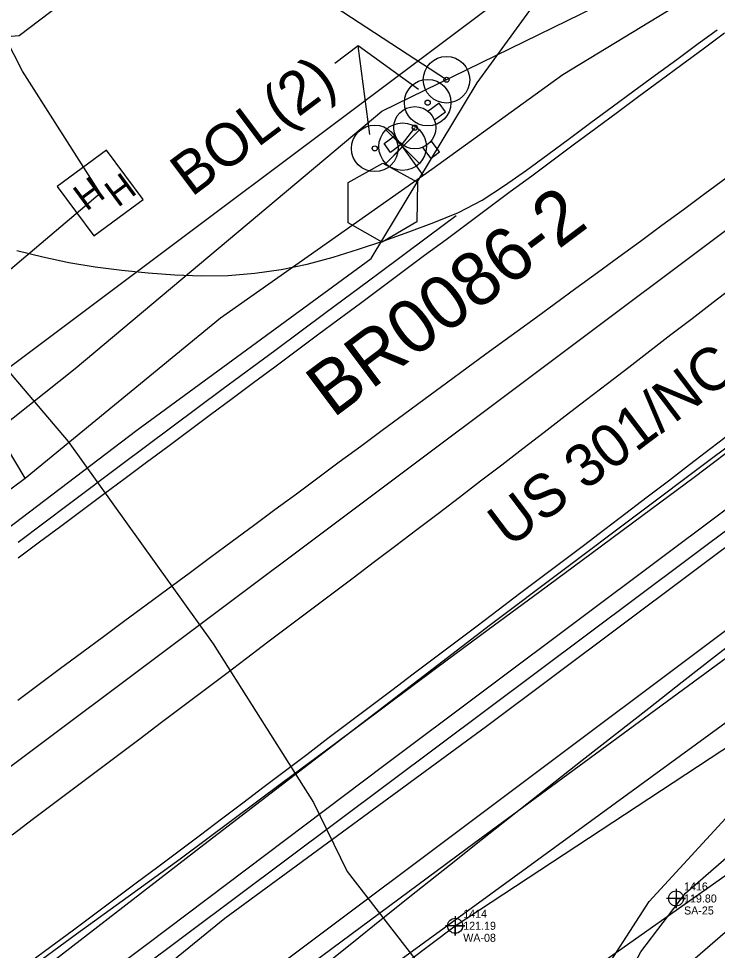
# Model space of a CAD drawing. Extents: x 2186615 to 2188822, y 629899 to 631820.
# Drawn here: x 2187187.8 to 2187253.2, y 630398.8 to 630486.1 of the extents above; entities that cross this region are included whole.
import ezdxf

# ---------------------------------------------------------------- set-up
doc = ezdxf.new("R2010")
doc.units = 0
for name, color, linetype in [('CTL Primary Horizontal and Vertical CELL', 7, 'Continuous'), ('CTL Primary Horizontal and Vertical Text', 7, 'Continuous'), ('Exist Environmental Wetland Boundary', 7, 'Continuous'), ('Exist Environmental Wetland Boundary Cogo Comment', 7, 'Continuous'), ('Exist Environmental Wetland Boundary Cogo Elevation', 7, 'Continuous'), ('Exist Environmental Wetland Boundary Cogo Number', 7, 'Continuous'), ('Exist Environmental Wetland Boundary Cogo Point CELL', 7, 'Continuous'), ('Exist Guardrail', 7, 'Continuous'), ('Exist Horizontal Alignment', 7, 'Continuous'), ('Exist Hydro Jurisdictional Stream or Body of Water', 7, 'Continuous'), ('Exist Other Culture Area Outline Leader', 7, 'Continuous'), ('Exist Other Culture Located Object CELL', 7, 'Continuous'), ('Exist Other Culture Located Object Leader', 7, 'Continuous'), ('Exist Other Culture Located Object Text', 7, 'Continuous'), ('Exist Right of Way Line', 7, 'Continuous'), ('Exist Roads EOP', 7, 'Continuous'), ('Exist Roads EOP Text', 7, 'Continuous'), ('Exist Roads EOT', 7, 'Continuous'), ('Exist Utilities Gas UG Line SUE LOS B', 7, 'Continuous'), ('Exist Utilities Sanitary Sewer UG Line', 7, 'Continuous'), ('Exist Utilities Telephone UG Cable SUE LOS C', 7, 'Continuous'), ('Exist Utilities Telephone UG FO SUE LOS B', 7, 'Continuous'), ('Exist Utilities TV Hand Hole CELL', 7, 'Continuous'), ('Exist Utilities TV UG FO Cable SUE LOS B', 7, 'Continuous'), ('Exist Utilities Water Fire Hydrant CELL', 7, 'Continuous'), ('Exist Utilities Water UG Line SUE LOS B', 7, 'Continuous'), ('Exist Utilities Water Valve CELL', 7, 'Continuous'), ('Exist Vegetation Woods Line', 7, 'Continuous'), ('Scratch_Level_1', 7, 'Continuous')]:
    doc.layers.add(name, color=color, linetype=linetype)

msp = doc.modelspace()

# ---------------------------------------------------------------- linework, layer by layer
at = {"layer": 'CTL Primary Horizontal and Vertical CELL'}
msp.add_line((2187221.866, 630468.879), (2187221.866, 630468.879), dxfattribs=at)
msp.add_lwpolyline([(2187218.634, 630470.75), (2187221.884, 630472.563), (2187225.134, 630470.775), (2187225.084, 630467.05), (2187221.834, 630465.163), (2187218.634, 630466.975)], close=True, dxfattribs=at)
at = {"layer": 'Exist Environmental Wetland Boundary'}
for points in [[(2187200.333, 630357.676), (2187218.012, 630369.88), (2187243.865, 630391.755), (2187268.738, 630413.3), (2187284.769, 630424.116), (2187304.062, 630440.889), (2187311.728, 630449.237), (2187310.985, 630450.407)], [(2187091.311, 630271.672), (2187085.676, 630287.812), (2187098.271, 630306.167), (2187117.246, 630318.391), (2187145.167, 630331.818), (2187167.383, 630352.861), (2187202.427, 630381.298), (2187228.671, 630401.09), (2187258.21, 630420.516), (2187282.166, 630435.853)]]:
    msp.add_lwpolyline(points, dxfattribs=at)
at = {"layer": 'Exist Environmental Wetland Boundary Cogo Point CELL'}
for points in [[(2187249.362, 630404.547), (2187249.362, 630402.747), (2187249.362, 630403.647), (2187250.262, 630403.647), (2187248.462, 630403.647)], [(2187228.671, 630401.99), (2187228.671, 630400.19), (2187228.671, 630401.09), (2187229.571, 630401.09), (2187227.771, 630401.09)]]:
    msp.add_lwpolyline(points, dxfattribs=at)
for centre in [(2187249.362, 630403.647), (2187228.671, 630401.09)]:
    msp.add_circle(centre, 0.703, dxfattribs=at)
at = {"layer": 'Exist Guardrail'}
msp.add_lwpolyline([(2187434.115, 630575.844), (2187413.642, 630560.327), (2187392.389, 630544.34), (2187371.189, 630528.329), (2187353.022, 630514.54), (2187332.378, 630498.862), (2187308.035, 630480.517), (2187282.875, 630461.57), (2187260.432, 630444.878), (2187240.787, 630430.164), (2187221.99, 630416.084), (2187199.867, 630399.404), (2187178.435, 630383.307), (2187159.654, 630369.054), (2187143.316, 630356.53), (2187128.809, 630345.412), (2187116.826, 630336.517)], dxfattribs=at)
at = {"layer": 'Exist Horizontal Alignment'}
msp.add_line((2187136.406, 630378.107), (2188520.855, 631416.042), dxfattribs=at)
at = {"layer": 'Exist Hydro Jurisdictional Stream or Body of Water'}
for points in [[(2187197.322, 630361.43), (2187213.945, 630373.562), (2187222.659, 630386.877), (2187241.705, 630395.38), (2187246.836, 630403.358), (2187255.086, 630412.327), (2187267.186, 630417.823), (2187275.409, 630422.294), (2187281.209, 630428.913), (2187281.92, 630435.898), (2187289.055, 630441.644), (2187305.984, 630451.32), (2187327.255, 630464.456), (2187344.34, 630479.914), (2187359.178, 630488.147), (2187368.792, 630495.674), (2187384.724, 630510.856), (2187399.768, 630521.857), (2187428.248, 630541.272), (2187449.565, 630557.041)], [(2187200.333, 630357.676), (2187217.66, 630373.541), (2187219.417, 630375.085), (2187222.068, 630380.972), (2187226.921, 630384.519), (2187239.946, 630392.223), (2187243.455, 630393.717), (2187246.058, 630398.658), (2187250.235, 630404.156), (2187257.633, 630410.563), (2187272.327, 630417.422), (2187280.629, 630425.711), (2187291.154, 630437.828), (2187309.311, 630449.202), (2187326.618, 630461.663), (2187344.871, 630475.57), (2187361.058, 630486.179), (2187383.779, 630505.824), (2187403.688, 630519.913), (2187435.685, 630540.516), (2187447.835, 630554.369)]]:
    msp.add_lwpolyline(points, dxfattribs=at)
at = {"layer": 'Exist Other Culture Area Outline Leader'}
msp.add_lwpolyline([(2187168.926, 630482.94), (2187187.799, 630484.536), (2187191.69, 630487.453)], dxfattribs=at)
at = {"layer": 'Exist Other Culture Located Object CELL'}
for centre, radius in [((2187227.853, 630480.376), 2.18), ((2187226.09, 630478.227), 2.18), ((2187227.853, 630480.376), 0.24), ((2187226.09, 630478.227), 0.24), ((2187221.132, 630473.943), 2.18), ((2187221.132, 630473.943), 0.24)]:
    msp.add_circle(centre, radius, dxfattribs=at)
at = {"layer": 'Exist Other Culture Located Object Leader'}
for points in [[(2187227.853, 630480.376), (2187217.435, 630487.187), (2187220.582, 630489.546)], [(2187220.664, 630475.256), (2187219.59, 630483.548), (2187217.402, 630481.907)], [(2187225.219, 630479.456), (2187219.59, 630483.548), (2187217.402, 630481.907)]]:
    msp.add_lwpolyline(points, dxfattribs=at)
at = {"layer": 'Exist Right of Way Line'}
for p, q in [((2187118.411, 630402.11), (2188502.827, 631440.021)), ((2187154.402, 630354.104), (2188538.851, 631392.039))]:
    msp.add_line(p, q, dxfattribs=at)
msp.add_arc((2189028.8, 628141.736), 2893.554, 125.65722, 135.708207, dxfattribs=at)
at = {"layer": 'Exist Roads EOP'}
for points in [[(2187187.603, 630464.38), (2187190.032, 630463.786), (2187192.475, 630463.257), (2187194.94, 630462.842), (2187197.422, 630462.539), (2187199.908, 630462.289), (2187202.4, 630462.098), (2187204.898, 630461.996), (2187207.397, 630462.034), (2187209.889, 630462.236), (2187212.363, 630462.597), (2187214.812, 630463.099), (2187217.228, 630463.739), (2187219.614, 630464.485), (2187221.979, 630465.293), (2187224.331, 630466.139), (2187226.673, 630467.014), (2187228.994, 630467.934), (2187231.212, 630469.087), (2187233.299, 630470.463), (2187235.339, 630471.908), (2187237.359, 630473.381), (2187239.369, 630474.867), (2187241.374, 630476.36), (2187243.38, 630477.852), (2187245.395, 630479.331), (2187247.411, 630480.81), (2187249.427, 630482.288), (2187251.443, 630483.766), (2187253.221, 630485.07)], [(2187187.729, 630437.045), (2187192.512, 630440.668), (2187197.316, 630444.262), (2187202.127, 630447.846), (2187206.939, 630451.431), (2187211.753, 630455.012), (2187216.569, 630458.591), (2187221.385, 630462.169), (2187226.201, 630465.747), (2187228.775, 630467.658)], [(2187255.836, 630446.736), (2187251.071, 630443.09), (2187246.246, 630439.524), (2187241.419, 630435.961), (2187236.591, 630432.398), (2187231.763, 630428.836), (2187226.945, 630425.261), (2187222.134, 630421.675), (2187217.324, 630418.089), (2187212.513, 630414.504), (2187207.703, 630410.918), (2187202.884, 630407.343), (2187198.03, 630403.816), (2187193.174, 630400.292), (2187188.329, 630396.753), (2187183.51, 630393.178)]]:
    msp.add_lwpolyline(points, dxfattribs=at)
at = {"layer": 'Exist Roads EOT'}
for points in [[(2187187.706, 630435.563), (2187189.71, 630437.058), (2187191.714, 630438.553), (2187193.718, 630440.047), (2187195.723, 630441.54), (2187197.729, 630443.033), (2187199.734, 630444.525), (2187201.739, 630446.018), (2187203.745, 630447.511), (2187205.75, 630449.003), (2187207.756, 630450.496), (2187209.761, 630451.989), (2187211.767, 630453.481), (2187213.772, 630454.974), (2187215.778, 630456.466), (2187217.783, 630457.959), (2187219.789, 630459.452), (2187221.795, 630460.943), (2187223.801, 630462.435), (2187225.808, 630463.926), (2187227.815, 630465.417), (2187229.822, 630466.907), (2187231.828, 630468.398), (2187233.835, 630469.889), (2187235.842, 630471.38), (2187237.848, 630472.871), (2187239.855, 630474.362), (2187241.862, 630475.852), (2187243.87, 630477.342), (2187245.879, 630478.829), (2187247.889, 630480.316), (2187249.898, 630481.802), (2187251.908, 630483.289), (2187253.918, 630484.775)], [(2187187.68, 630422.229), (2187189.685, 630423.723), (2187191.69, 630425.217), (2187193.695, 630426.71), (2187195.701, 630428.201), (2187197.71, 630429.69), (2187199.719, 630431.177), (2187201.729, 630432.663), (2187203.739, 630434.149), (2187205.749, 630435.636), (2187207.759, 630437.122), (2187209.769, 630438.609), (2187211.78, 630440.095), (2187213.79, 630441.582), (2187215.8, 630443.068), (2187217.81, 630444.555), (2187219.82, 630446.041), (2187221.83, 630447.528), (2187223.84, 630449.014), (2187225.85, 630450.501), (2187227.86, 630451.986), (2187229.873, 630453.469), (2187231.892, 630454.943), (2187233.913, 630456.415), (2187235.934, 630457.887), (2187237.955, 630459.359), (2187239.976, 630460.83), (2187241.997, 630462.302), (2187244.017, 630463.774), (2187246.035, 630465.25), (2187248.046, 630466.735), (2187250.056, 630468.221), (2187252.065, 630469.708), (2187254.073, 630471.198)], [(2187187.169, 630409.625), (2187189.165, 630411.129), (2187191.162, 630412.633), (2187193.159, 630414.138), (2187195.155, 630415.642), (2187197.152, 630417.147), (2187199.149, 630418.651), (2187201.145, 630420.156), (2187203.141, 630421.661), (2187205.136, 630423.167), (2187207.131, 630424.674), (2187209.126, 630426.18), (2187211.122, 630427.687), (2187213.117, 630429.193), (2187215.112, 630430.699), (2187217.107, 630432.206), (2187219.102, 630433.712), (2187221.097, 630435.219), (2187223.092, 630436.725), (2187225.087, 630438.232), (2187227.081, 630439.741), (2187229.069, 630441.256), (2187231.052, 630442.778), (2187233.035, 630444.301), (2187235.017, 630445.825), (2187236.999, 630447.348), (2187238.981, 630448.872), (2187240.963, 630450.396), (2187242.945, 630451.919), (2187244.927, 630453.443), (2187246.909, 630454.967), (2187248.891, 630456.49), (2187250.873, 630458.014), (2187252.855, 630459.538), (2187254.837, 630461.061)], [(2187254.602, 630447.322), (2187252.616, 630445.804), (2187250.629, 630444.287), (2187248.642, 630442.771), (2187246.654, 630441.254), (2187244.667, 630439.738), (2187242.679, 630438.222), (2187240.69, 630436.707), (2187238.698, 630435.197), (2187236.701, 630433.692), (2187234.705, 630432.187), (2187232.709, 630430.682), (2187230.713, 630429.176), (2187228.718, 630427.67), (2187226.722, 630426.164), (2187224.727, 630424.658), (2187222.732, 630423.152), (2187220.737, 630421.646), (2187218.743, 630420.138), (2187216.749, 630418.629), (2187214.756, 630417.12), (2187212.763, 630415.61), (2187210.77, 630414.101), (2187208.777, 630412.592), (2187206.784, 630411.083), (2187204.791, 630409.574), (2187202.794, 630408.07), (2187200.791, 630406.574), (2187198.787, 630405.08), (2187196.782, 630403.586), (2187194.777, 630402.093), (2187192.773, 630400.599), (2187190.768, 630399.105), (2187188.763, 630397.612)]]:
    msp.add_lwpolyline(points, dxfattribs=at)
at = {"layer": 'Exist Utilities Gas UG Line SUE LOS B'}
msp.add_lwpolyline([(2187126.474, 630392.391), (2187146.749, 630408.061), (2187165.948, 630422.166), (2187183.003, 630435.52), (2187198.842, 630447.531), (2187220.79, 630463.611), (2187230.742, 630480.093), (2187238.842, 630491.282), (2187252.932, 630500.782), (2187264.616, 630507.024), (2187278.901, 630518.022), (2187291.156, 630525.789), (2187304.759, 630536.934), (2187314.395, 630544.202), (2187331.496, 630558.331), (2187350.478, 630574.64)], dxfattribs=at)
at = {"layer": 'Exist Utilities Sanitary Sewer UG Line'}
msp.add_line((2186953.526, 630213.342), (2187280.261, 630457.751), dxfattribs=at)
at = {"layer": 'Exist Utilities Telephone UG Cable SUE LOS C'}
msp.add_lwpolyline([(2187048.711, 630267.562), (2187045.354, 630278.254), (2187057.018, 630287.248), (2187078.192, 630303.416), (2187102.037, 630322.514), (2187119.945, 630336.137), (2187137.937, 630349.883), (2187161.709, 630367.862), (2187186.024, 630384.639), (2187207.077, 630401.804), (2187231.599, 630419.787), (2187256.848, 630438.711), (2187278.852, 630453.798), (2187296.978, 630467.542), (2187304.942, 630472.732), (2187317.617, 630478.554), (2187327.51, 630484.53), (2187332.683, 630485.862), (2187337.992, 630482.804), (2187346.28, 630476.796)], dxfattribs=at)
at = {"layer": 'Exist Utilities Telephone UG FO SUE LOS B'}
msp.add_line((2187193.045, 630453.322), (2187221.787, 630477.44), dxfattribs=at)
for points in [[(2187221.787, 630477.44), (2187244.494, 630488.549), (2187260.766, 630497.303), (2187273.174, 630505.002), (2187293.431, 630514.995), (2187319.925, 630532.538), (2187378.478, 630575.929), (2187483.974, 630656.576), (2187503.962, 630671.26), (2187608.063, 630745.856)], [(2187129.463, 630527.757), (2187139.462, 630503.378), (2187147.833, 630484.704), (2187152.044, 630478.591), (2187166.914, 630468.201), (2187180.789, 630460.122), (2187192.399, 630446.464), (2187206.004, 630427.517), (2187215.398, 630412.656), (2187218.537, 630406.182), (2187228.538, 630393.279)], [(2187049.385, 630270.146), (2187042.504, 630278.367), (2187044.061, 630284.337), (2187057.315, 630294.022), (2187075.644, 630307.116), (2187098.729, 630326.668), (2187116.947, 630341.492), (2187134.442, 630355.423), (2187157.809, 630373.051), (2187181.899, 630390.785), (2187205.122, 630408.701), (2187231.973, 630429.319), (2187252.444, 630444.703), (2187272.54, 630459.689), (2187294.094, 630476.316), (2187309.645, 630487.965), (2187327.188, 630501.034), (2187332.668, 630500.224), (2187340.344, 630491.389), (2187346.28, 630476.796)], [(2187121.863, 630401.099), (2187141.283, 630415.488), (2187160.796, 630429.17), (2187178.34, 630441.634), (2187193.045, 630453.322)]]:
    msp.add_lwpolyline(points, dxfattribs=at)
at = {"layer": 'Exist Utilities TV Hand Hole CELL'}
msp.add_line((2187195.404, 630469.76), (2187195.404, 630469.76), dxfattribs=at)
msp.add_lwpolyline([(2187194.804, 630465.738), (2187199.425, 630469.16), (2187196.004, 630473.781), (2187191.383, 630470.36), (2187194.804, 630465.738)], dxfattribs=at)
at = {"layer": 'Exist Utilities TV UG FO Cable SUE LOS B'}
msp.add_lwpolyline([(2187116.728, 630410.236), (2187135.272, 630423.284), (2187155.78, 630437.629), (2187172.033, 630450.398), (2187187.013, 630462.628), (2187195.404, 630469.76), (2187188.115, 630481.182), (2187177.235, 630502.526), (2187165.507, 630524.628), (2187155.034, 630546.981)], dxfattribs=at)
at = {"layer": 'Exist Utilities Water Fire Hydrant CELL'}
msp.add_line((2187224.885, 630475.883), (2187224.885, 630475.883), dxfattribs=at)
for points in [[(2187226.729, 630476.605), (2187227.766, 630477.369), (2187227.157, 630478.194), (2187226.101, 630477.415)], [(2187223.65, 630474.336), (2187222.613, 630473.572), (2187222.005, 630474.397), (2187223.062, 630475.176)], [(2187225.607, 630474.039), (2187226.371, 630473.003), (2187227.196, 630473.611), (2187226.433, 630474.647)]]:
    msp.add_lwpolyline(points, dxfattribs=at)
for radius in [1.977, 0.243]:
    msp.add_circle((2187224.885, 630475.883), radius, dxfattribs=at)
at = {"layer": 'Exist Utilities Water UG Line SUE LOS B'}
for points in [[(2187188.37, 630443.024), (2187206.689, 630458.058), (2187226.474, 630471.999), (2187238.766, 630480.882), (2187255.867, 630491.296), (2187266.081, 630498.059), (2187295.46, 630519.284), (2187306.869, 630527.171), (2187321.342, 630537.501), (2187340.106, 630551.443), (2187356.85, 630563.988), (2187378.548, 630580.267)], [(2187181.754, 630438.125), (2187188.37, 630443.024), (2187184.928, 630448.763), (2187177.597, 630459.458), (2187168.655, 630475.532), (2187158.99, 630495.239), (2187152.399, 630508.064), (2187139.391, 630535.221)], [(2187225.667, 630471.43), (2187223.636, 630474.256), (2187224.885, 630475.883)]]:
    msp.add_lwpolyline(points, dxfattribs=at)
at = {"layer": 'Exist Utilities Water Valve CELL'}
msp.add_lwpolyline([(2187225.317, 630475.683), (2187222.167, 630472.533), (2187223.742, 630474.108), (2187225.317, 630472.533), (2187222.167, 630475.683)], dxfattribs=at)
msp.add_circle((2187223.742, 630474.108), 2.227, dxfattribs=at)
at = {"layer": 'Exist Vegetation Woods Line'}
for points in [[(2187105.726, 630299.086), (2187150.799, 630331.829), (2187206.105, 630372.034), (2187256.074, 630407.258), (2187300.913, 630439.289), (2187349.475, 630473.877), (2187396.874, 630507.865), (2187440.691, 630538.214), (2187466.075, 630555.071), (2187474.722, 630557.755), (2187481.166, 630558.923), (2187486.051, 630559.676), (2187489.303, 630561.136), (2187491.384, 630563.953), (2187492.451, 630570.166), (2187494.251, 630572.315)], [(2187230.496, 630408.889), (2187277.266, 630443.245), (2187318.865, 630473.262), (2187330.634, 630477.313), (2187307.147, 630458.864), (2187234.208, 630405.639), (2187193.004, 630375.627), (2187170.079, 630359.227), (2187132.552, 630332.436), (2187105.521, 630312.125)], [(2187103.491, 630315.876), (2187138.523, 630340.833), (2187186.53, 630376.001), (2187214.458, 630397), (2187230.496, 630408.889)]]:
    msp.add_lwpolyline(points, dxfattribs=at)
at = {"layer": 'Scratch_Level_1'}
msp.add_arc((2189028.8, 628141.736), 2815.554, 125.65722, 135.708207, dxfattribs=at)

# ---------------------------------------------------------------- texts
at = {"layer": 'CTL Primary Horizontal and Vertical Text'}
msp.add_text('BR0086-2', height=5, rotation=36.85926, dxfattribs=at).set_placement((2187217.218, 630448.604))
at = {"layer": 'Exist Environmental Wetland Boundary Cogo Comment'}
for s, p in [('SA-25', (2187250.112, 630402.147)), ('WA-08', (2187229.421, 630399.59))]:
    msp.add_text(s, height=0.75, dxfattribs=at).set_placement(p)
at = {"layer": 'Exist Environmental Wetland Boundary Cogo Elevation'}
for s, p in [('119.80', (2187250.112, 630403.272)), ('121.19', (2187229.421, 630400.715))]:
    msp.add_text(s, height=0.75, dxfattribs=at).set_placement(p)
at = {"layer": 'Exist Environmental Wetland Boundary Cogo Number'}
for s, p in [('1416', (2187250.112, 630404.397)), ('1414', (2187229.421, 630401.84))]:
    msp.add_text(s, height=0.75, dxfattribs=at).set_placement(p)
at = {"layer": 'Exist Other Culture Located Object Text'}
msp.add_text('BOL(2)', height=4, rotation=36.85926, dxfattribs=at).set_placement((2187203.962, 630469.331))
at = {"layer": 'Exist Roads EOP Text'}
msp.add_text("US 301/NC 96/S BRIGHTLEAF BLVD 32' BST", height=4, rotation=37.12382, dxfattribs=at).set_placement((2187233.734, 630436.435))
at = {"layer": 'Exist Utilities TV Hand Hole CELL'}
for p in [(2187197.048, 630468.354), (2187194.11, 630467.996)]:
    msp.add_text('H', height=2.5, rotation=36.51465, dxfattribs=at).set_placement(p)

doc.saveas('drawing.dxf')
